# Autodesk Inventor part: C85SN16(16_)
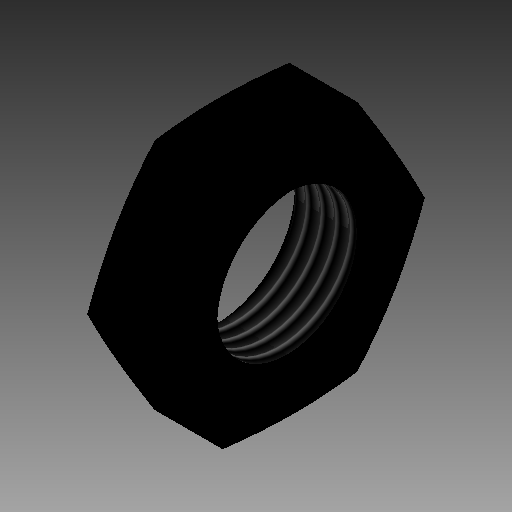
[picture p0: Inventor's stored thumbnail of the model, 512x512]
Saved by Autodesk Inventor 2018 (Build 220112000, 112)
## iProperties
Category: PARTsolutions
Company: SMC
Part Number: C85SN16(16_)
Material: Generic
Catalog Web Link: www.cadenas.de
Description: C85/CD85 MOUNTING_NUT-ISO Standard Air Cylinder:Standard Type Double Acting Single Rod
Vendor: SMC
Document SubType Name: Modeling
Designer: partserver
Manufacturer: SMC
Mass: 2.64727 g
Surface Area: 16.331 cm^2
Volume: 2.64727 cm^3
Density: 1 g/cm^3
Appearance: PSOLRGB-0-0-0
PSOL_IDENT_0: {$CADENAS_DATA\23d-libs\smc_jp\actuator\standard_air_cylinder\c85\c85\parts\c85_m_nut.prj},178 {VTYP=
PSOL_IDENT_1: 3D},{NB=C85SN16(16_)},{LINA=C85SN16},{NN=C85/CD85 MOUNTING_NUT},{DATE=09.12.2020 02:57:06},{GEOMDATE=
PSOL_IDENT_2: 28.04.2020 08:30:14},{VERSION=},{LINEID=40},{WBVAR=OMSC},{WBNUMERIC=}  {NB=C85SN16(16_)},{LINA=C85SN
PSOL_IDENT_3: 16},{KT=DUMMY},{MODEL=C85SN16},{BORE=16},{OMSC=},{BE=M16x1.5},{BED=16},{BEJ=1.500},{KV=24},{KW=8}
NB: C85SN16(16_)
NN: C85/CD85 MOUNTING_NUT
NT: ISO Standard Air Cylinder:Standard Type Double Acting Single Rod
NBSYN: $MODEL.($BORE._$OMSC.)
LINA: C85SN16
CATALOG: SMC (JP
BORE: 16
OMSC: (-) Without order
BE: M16x1.5
BED: 16
BEJ: 1.5
KV: 24
KW: 8
SUPPLIER: SMC
ARTICLENO: C85SN16(16_)
BOMINFO: C85SN16
CREATOR: CADENAS GmbH
Title: C85SN16
Author: Cadenas PARTsolutions
Comments: ISO Standard Air Cylinder:Standard Type Double Acting Single Rod
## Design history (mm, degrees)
sketch "Sketch_1"
  geometry: L1 (8, 0)-(0, 0); L2 (0, 12)-(0, 8); L3 (0, 8)-(0.812, 7.188); L4 (0.812, 7.188)-(7.188, 7.188); L5 (7.188, 7.188)-(8, 8); L6 (8, 8)-(8, 12); L7 (8, 12)-(4, 26.928); L8 (4, 26.928)-(0, 12)
  constraints: 16 end point
revolve "Revolution1" sketch "Sketch_1" stored, may be unused: angle "d0" = 360 deg
thread "Thread1" dims "d1" = 6.376, "d2" = 0
sketch "Sketch_2"
  geometry: L1 (-6.928, 12)-(-13.856, 0); L2 (-13.856, 0)-(-6.928, -12); L3 (-6.928, -12)-(6.928, -12); L4 (6.928, -12)-(13.856, 0); L5 (13.856, 0)-(6.928, 12); L6 (6.928, 12)-(-6.928, 12); C1 r 36 at (0, 0); 1 further point
  constraints: 12 end point, 1 centre point
extrude "Extrusion1" cut sketch "Sketch_2" distance "d3" = 8; taper "d4" = 0 deg
node "MNUT_BODY_XY"
node "MNUT_BODY_YZ"
node "MNUT_BODY_ZX"
node "MNUT_BODY_X"
node "MNUT_BODY_Y"
node "MNUT_BODY_Z"
node "MNUT_BODY_Center"
body "Solid1"
